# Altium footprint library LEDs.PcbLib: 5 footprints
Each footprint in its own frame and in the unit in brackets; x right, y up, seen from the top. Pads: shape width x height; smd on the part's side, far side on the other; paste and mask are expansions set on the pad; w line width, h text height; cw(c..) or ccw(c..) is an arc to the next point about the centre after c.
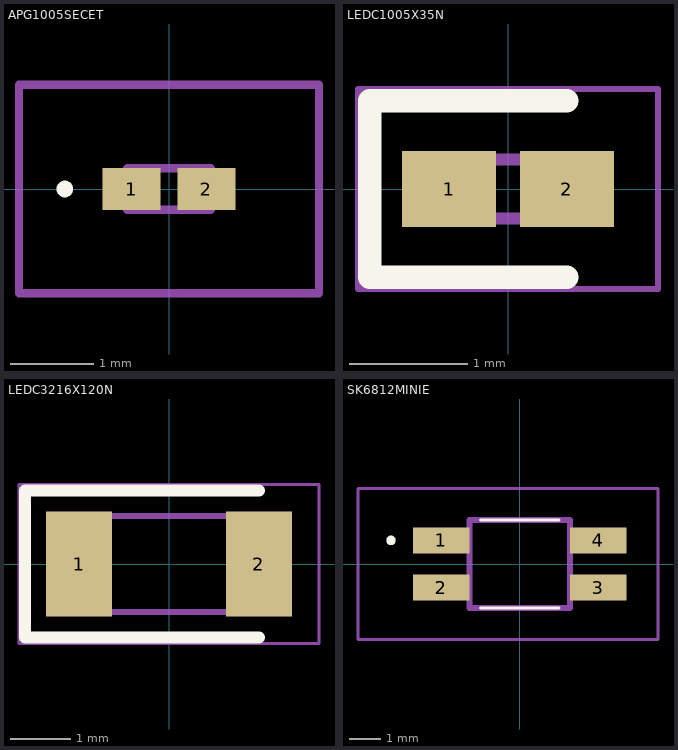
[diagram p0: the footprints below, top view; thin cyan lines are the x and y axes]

## APG1005SECET [mm]
pads (2):
  rect 0.7x0.5 smd: 1(-0.45,0) 2(0.45,0)
Top Overlay:
  lines w0.1: -1.3,0 ccw(c-1.25,0) -1.2,0 ccw(c-1.25,0) -1.3,0
Mechanical 13:
  lines w0.1: -0.5,-0.25 -0.5,0.25 0.5,0.25 0.5,-0.25 -0.5,-0.25
Mechanical 15:
  lines w0.1: -1.8,-1.25 -1.8,1.25 1.8,1.25 1.8,-1.25 -1.8,-1.25
3D body "APG1005SEC_E-T.stp": height 0.35, standoff 0, extent -0.5,-0.25 0.5,0.25

## LEDC1005X35N [mm]
pads (2):
  rect 0.8x0.65 smd: 1(-0.5,0) 2(0.5,0)
Top Overlay:
  lines w0.2: 0.5,-0.75 -1.175,-0.75 -1.175,0.75 0.5,0.75
Mechanical 13:
  lines w0.1: -0.5,0.083 -0.333,0.25 ; -0.5,-0.25 -0.5,0.25 0.5,0.25 0.5,-0.25 -0.5,-0.25
Mechanical 15:
  lines w0.05: -1.275,-0.85 -1.275,0.85 1.275,0.85 1.275,-0.85 -1.275,-0.85
3D body "VLMG1500-GS08.stp": height 0.5, standoff 0, extent -0.53,-0.17 0.47,0.18

## LEDC3216X120N [mm]
pads (2):
  rect 1.1x1.75 smd: 1(-1.5,0) 2(1.5,0)
Top Overlay:
  lines w0.2: 1.5,-1.225 -2.4,-1.225 -2.4,1.225 1.5,1.225
Mechanical 13:
  lines w0.1: -1.6,0.267 -1.067,0.8 ; -1.6,-0.8 1.6,-0.8 1.6,0.8 -1.6,0.8 -1.6,-0.8
Mechanical 15:
  lines w0.05: -2.5,-1.325 2.5,-1.325 2.5,1.325 -2.5,1.325 -2.5,-1.325
3D body "HSMR-C150.stp": height 1.1, standoff 0, extent -1.6,-0.8 1.6,0.8

## PCBComponent_1 [mm]

## SK6812MINIE [mm]
pads (4):
  rect 1.8x0.82 smd: 1(-2.5,0.75) 2(-2.5,-0.75) 3(2.5,-0.75) 4(2.5,0.75)
Top Overlay:
  lines w0.1: -1.25,-1.4 1.25,-1.4 -1.25,-1.4 ; -1.25,1.4 1.25,1.4 -1.25,1.4
  lines w0.2: -4.1,0.7 ccw(c-4.1,0.75) -4.1,0.8 ; -4.1,0.7 cw(c-4.1,0.75) -4.1,0.8 ; -4.1,0.7 ccw(c-4.1,0.75) -4.1,0.8
Mechanical 13:
  lines w0.2: -1.6,-1.4 -1.6,1.4 1.6,1.4 1.6,-1.4 -1.6,-1.4
Mechanical 15:
  lines w0.1: -5.15,-2.4 -5.15,2.4 4.4,2.4 4.4,-2.4 -5.15,-2.4
3D body "SK6812MINI-E.stp": height 0.97, standoff -0.81, extent -2.94,-1.4 2.94,1.4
